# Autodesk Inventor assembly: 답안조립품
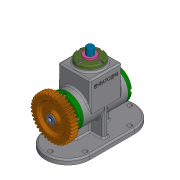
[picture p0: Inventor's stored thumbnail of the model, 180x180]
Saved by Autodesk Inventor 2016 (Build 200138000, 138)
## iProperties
Created: 2020-01
Part Number: 답안조립품
Document SubType Name: Assembly
Designer: user
Mass: 2018.69 g
Surface Area: 1737.06 cm^2
Volume: 591.723 cm^3
Density: 3.41155 g/cm^3
Author: user
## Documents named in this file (18)
- C:\Users\user\Desktop\600104V1039\답안조립품.iam
- C:\Users\user\Desktop\600104V1039\본체.ipt
- C:\Users\user\Desktop\600104V1039\편심축.ipt
- C:\Users\user\Desktop\600104V1039\키 4x4x12.ipt
- C:\Users\user\Desktop\600104V1039\베어링 6203.ipt
- C:\Users\user\Desktop\600104V1039\뒤커버.ipt
- C:\Users\user\Desktop\600104V1039\앞커버.ipt
- C:\Users\user\Desktop\600104V1039\오일 실 17 30 5.ipt
- C:\Users\user\Desktop\600104V1039\볼트 M4.ipt
- C:\Users\user\Desktop\600104V1039\스퍼기어.ipt
- C:\Users\user\Desktop\600104V1039\평와셔.ipt
- C:\Users\user\Desktop\600104V1039\스프링와셔.ipt
- C:\Users\user\Desktop\600104V1039\스프링조립용 와셔.ipt
- C:\Users\user\Desktop\600104V1039\슬라이더.ipt
- C:\Users\user\Desktop\600104V1039\멈춤링.ipt
- C:\Users\user\Desktop\600104V1039\부시.ipt
- C:\Users\user\Desktop\600104V1039\상부커버.ipt
- C:\Users\user\Desktop\600104V1039\가변스프링.ipt
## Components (1 placed, 1 different names)
1. 가변스프링:1
